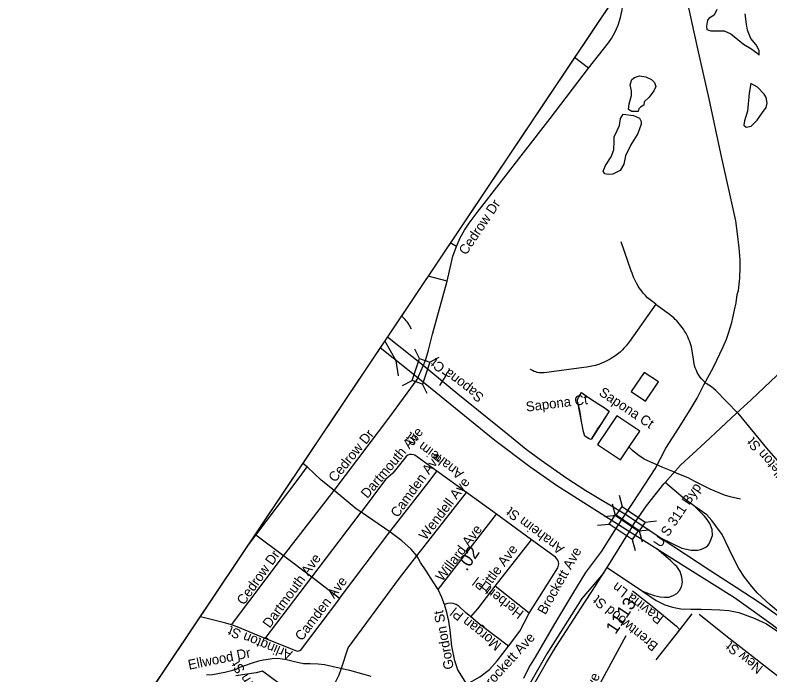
# Model space of a CAD drawing. Extents: x 1715610 to 1720914, y 798298 to 802505.
# Drawn here: x 1715610 to 1715768.9, y 799566.4 to 799705.3 of the extents above; entities that cross this region are included whole.
import ezdxf

# ---------------------------------------------------------------- set-up
doc = ezdxf.new("R2010")
doc.units = 0
doc.layers.add('Default', color=7, linetype='Continuous')
doc.layers.add('Prop DSN Text', color=7, linetype='Continuous')

msp = doc.modelspace()

# ---------------------------------------------------------------- linework, layer by layer
at = {"layer": 'Default'}
for p, q in [((1715825.88, 799842.99), (1715610.03, 799520.5)), ((1715825.88, 799842.99), (1715610.03, 799520.5)), ((1715730.7, 799694.14), (1715727.74, 799696.37)), ((1715695.16, 799633.01), (1715694.16, 799635.02)), ((1715697.32, 799632.28), (1715699.28, 799633.29)), ((1715694.92, 799629.27), (1715695.91, 799631.51)), ((1715700.72, 799629.47), (1715699.9, 799629.99)), ((1715691.58, 799627.37), (1715693.58, 799628.37)), ((1715700.72, 799629.47), (1715699.33, 799627.31)), ((1715696.75, 799625.63), (1715695.75, 799627.64)), ((1715705.01, 799604.81), (1715698.76, 799609.34)), ((1715666.55, 799591.48), (1715677.16, 799605.23)), ((1715694.6, 799591.45), (1715705.01, 799604.81)), ((1715711.32, 799600.23), (1715705.01, 799604.81)), ((1715737.16, 799604.25), (1715737.82, 799601.89)), ((1715735.69, 799602.4), (1715736.36, 799600.05)), ((1715672.49, 799586.97), (1715682.88, 799600.66)), ((1715688.9, 799596.53), (1715682.88, 799600.66)), ((1715699.1, 799584.38), (1715711.32, 799600.23)), ((1715718.75, 799594.88), (1715711.32, 799600.23)), ((1715734.11, 799599.79), (1715736.54, 799600.02)), ((1715732.64, 799597.94), (1715735.08, 799598.17)), ((1715742.62, 799598.6), (1715745.06, 799598.83)), ((1715678.28, 799582.53), (1715688.9, 799596.53)), ((1715741.16, 799596.75), (1715743.59, 799596.98)), ((1715741.37, 799596.77), (1715742.04, 799594.41)), ((1715666.55, 799591.48), (1715660.68, 799595.85)), ((1715711.09, 799585.07), (1715718.75, 799594.88)), ((1715739.91, 799594.92), (1715740.57, 799592.57)), ((1715655.57, 799576.93), (1715666.55, 799591.48)), ((1715672.49, 799586.97), (1715666.55, 799591.48)), ((1715734.62, 799589.05), (1715742.05, 799584.05)), ((1715662.69, 799574.11), (1715672.49, 799586.97)), ((1715678.28, 799582.53), (1715672.49, 799586.97)), ((1715718.2, 799579.41), (1715711.09, 799585.07)), ((1715749.96, 799575.92), (1715752.53, 799579.24)), ((1715649.05, 799578.61), (1715648.94, 799578.63)), ((1715744.98, 799569.62), (1715749.96, 799575.92))]:
    msp.add_line(p, q, dxfattribs=at)
for points in [[(1715730.7, 799694.14), (1715734.91, 799699.49), (1715735.54, 799700.43), (1715736.24, 799701.66), (1715736.94, 799703.2), (1715737.47, 799704.81), (1715737.83, 799706.47), (1715737.98, 799708.09), (1715737.93, 799709.22), (1715737.76, 799710.32), (1715737.57, 799711.06)], [(1715717.08, 799565.74), (1715718.15, 799567.91), (1715719.59, 799570.15), (1715723.6, 799577.2), (1715727.45, 799583.47), (1715730.16, 799587.94), (1715733.51, 799592.45), (1715736.58, 799597.36), (1715738.34, 799600.02), (1715741.46, 799604.77), (1715744.75, 799609.77), (1715747, 799614.15), (1715749.77, 799618.48), (1715752.3, 799622.54), (1715753.57, 799624.68), (1715755.02, 799627.48), (1715757.02, 799631.23), (1715759.08, 799635.51), (1715759.75, 799637.1), (1715760.18, 799638.34), (1715760.91, 799640.63), (1715761.12, 799641.56), (1715761.46, 799643.19), (1715761.8, 799644.74), (1715762.01, 799646.51), (1715762.31, 799647.36), (1715762.54, 799649.97), (1715762.67, 799652.27), (1715762.61, 799653.8), (1715762.46, 799656.35), (1715762.11, 799659.28), (1715761.7, 799662), (1715758.56, 799676.22), (1715756.12, 799687.68), (1715753.74, 799698.23), (1715751.33, 799709.2)], [(1715757.72, 799706.49), (1715757.2, 799705.28), (1715756.13, 799704.65), (1715755.74, 799704.27), (1715755.53, 799703), (1715755.62, 799702.3), (1715756.44, 799702.03), (1715759.25, 799702), (1715760.68, 799701.39), (1715762.15, 799700.2), (1715763.33, 799699.2), (1715764.91, 799698.28), (1715766.15, 799697.38), (1715766.62, 799696.92), (1715766.61, 799697.85), (1715766.02, 799699.1), (1715764.91, 799700.4), (1715764.15, 799702.12), (1715763.94, 799703.39), (1715763.71, 799705.6)], [(1715746.87, 799606.94), (1715750.09, 799610.55), (1715755.24, 799615.32), (1715761.84, 799621.51), (1715764.95, 799624.35), (1715775.71, 799634.47), (1715778.64, 799637.42), (1715780.62, 799639.61), (1715793.86, 799657.02), (1715808.39, 799674), (1715821.8, 799689.38), (1715825.57, 799693.86), (1715826.9, 799695.32), (1715830.61, 799699.38), (1715831.51, 799700.23)], [(1715702.94, 799656.59), (1715703.74, 799658.43), (1715704.63, 799660.04), (1715705.61, 799661.5), (1715707.28, 799663.78), (1715722.64, 799683.54), (1715730.7, 799694.14)], [(1715741.2, 799685.01), (1715739.83, 799685.06), (1715739.13, 799685.44), (1715739.26, 799686.66), (1715739.8, 799688.39), (1715739.76, 799689.37), (1715739.51, 799690.67), (1715739.87, 799691.74), (1715740.41, 799692.16), (1715741.43, 799692.52), (1715742.78, 799692.31), (1715743.98, 799691.77), (1715744.58, 799691.11), (1715744.9, 799690.28), (1715744.46, 799689.36), (1715743.47, 799688.02), (1715742.41, 799687.08), (1715742.34, 799686.34), (1715741.64, 799685.94), (1715741.3, 799685.56), (1715741.2, 799685.01)], [(1715767.72, 799688.66), (1715766.29, 799690.14), (1715764.9, 799690.92), (1715764.56, 799688.87), (1715764.16, 799685.1), (1715763.55, 799683.09), (1715763.43, 799682.14), (1715763.9, 799681.75), (1715764.92, 799681.95), (1715766.21, 799683.22), (1715767.34, 799684.81), (1715768.14, 799685.89), (1715768.31, 799686.8), (1715768.13, 799687.95), (1715767.72, 799688.66)], [(1715738.03, 799684.44), (1715740.21, 799684.19), (1715741.48, 799683.61), (1715741.82, 799682.95), (1715741.83, 799682.33), (1715741.07, 799680.4), (1715739.66, 799678.04), (1715738.51, 799675.67), (1715738.13, 799673.93), (1715737.4, 799672.59), (1715735.84, 799671.81), (1715734.85, 799671.77), (1715734.15, 799671.89), (1715733.77, 799672.49), (1715734.32, 799673.69), (1715735.52, 799675.5), (1715736.07, 799676.96), (1715736.13, 799678.75), (1715736.15, 799679.69), (1715736.78, 799681.01), (1715737.24, 799682.09), (1715737.42, 799683.54), (1715738.03, 799684.44)], [(1715700.95, 799649.3), (1715702.19, 799654.57), (1715702.94, 799656.59)], [(1715702.94, 799656.59), (1715701.63, 799657.35)], [(1715744.86, 799644.46), (1715744.51, 799644.73), (1715743.67, 799645.35), (1715743.16, 799645.81), (1715742.69, 799646.3), (1715742.22, 799646.81), (1715741.94, 799647.17), (1715741.67, 799647.54), (1715741.4, 799647.91), (1715741.15, 799648.29), (1715740.81, 799648.89), (1715740.6, 799649.3), (1715740.4, 799649.7), (1715740.21, 799650.12), (1715740.04, 799650.55), (1715739.88, 799650.99), (1715739.72, 799651.52), (1715737.56, 799657.61)], [(1715700.95, 799649.3), (1715696.95, 799650.36)], [(1715695.91, 799631.51), (1715696.38, 799632.58), (1715697.05, 799634.78), (1715697.9, 799638.16), (1715700.95, 799649.3)], [(1715744.86, 799644.46), (1715739.32, 799636.6), (1715739.06, 799636.24), (1715738.63, 799635.7), (1715738.17, 799635.19), (1715737.84, 799634.87), (1715737.35, 799634.39), (1715736.82, 799633.95), (1715736.28, 799633.54), (1715735.9, 799633.28), (1715735.31, 799632.92), (1715734.72, 799632.59), (1715734.31, 799632.38), (1715733.9, 799632.2), (1715733.48, 799632.02), (1715733.05, 799631.86), (1715732.63, 799631.7), (1715732.18, 799631.58), (1715731.74, 799631.47), (1715731.07, 799631.32), (1715730.4, 799631.21), (1715729.7, 799631.14), (1715721.37, 799630.01), (1715721, 799629.99), (1715720.64, 799629.99), (1715720.29, 799630.03), (1715719.94, 799630.09), (1715719.6, 799630.19), (1715719.27, 799630.32), (1715718.94, 799630.48), (1715718.64, 799630.67), (1715718.63, 799630.68), (1715718.62, 799630.69), (1715718.6, 799630.7), (1715718.6, 799630.7), (1715718.59, 799630.71), (1715718.57, 799630.72), (1715718.56, 799630.72), (1715718.55, 799630.73), (1715718.54, 799630.74), (1715718.53, 799630.75), (1715718.52, 799630.75), (1715718.51, 799630.76), (1715718.51, 799630.77), (1715718.49, 799630.78), (1715718.48, 799630.78)], [(1715762.15, 799621.53), (1715757.53, 799626.26), (1715757.08, 799626.67), (1715756.61, 799627.06), (1715756.07, 799627.44), (1715755.5, 799627.79), (1715755.3, 799627.94), (1715755.05, 799628.19), (1715754.78, 799628.45), (1715754.52, 799628.73), (1715754.22, 799629.13), (1715753.94, 799629.53), (1715753.62, 799630.07), (1715753.42, 799630.51), (1715753.2, 799631.09), (1715753.05, 799631.57), (1715752.97, 799631.94), (1715752.88, 799632.42), (1715752.84, 799632.92), (1715752.37, 799635.48), (1715752.31, 799635.7), (1715752.11, 799636.35), (1715751.94, 799636.78), (1715751.77, 799637.19), (1715751.59, 799637.6), (1715751.39, 799638.01), (1715751.17, 799638.4), (1715750.94, 799638.8), (1715750.7, 799639.17), (1715750.45, 799639.55), (1715750.18, 799639.91), (1715749.9, 799640.26), (1715749.61, 799640.61), (1715749.3, 799640.94), (1715748.99, 799641.27), (1715748.66, 799641.57), (1715748.15, 799642.02), (1715747.79, 799642.3), (1715745.2, 799644.22), (1715744.86, 799644.46)], [(1715693.43, 799639.2), (1715693.03, 799639.99), (1715692.75, 799640.47), (1715692.57, 799640.73), (1715692.37, 799640.98), (1715692.16, 799641.22), (1715691.95, 799641.45), (1715691.69, 799641.69), (1715691.42, 799641.91), (1715691.34, 799641.98)], [(1715688.42, 799637.62), (1715695.89, 799631.6), (1715703.19, 799625.59), (1715713.76, 799617.08), (1715717.61, 799613.92), (1715720.77, 799611.62), (1715726.13, 799607.84), (1715730.13, 799605.26), (1715738.69, 799600.09), (1715740.69, 799598.75)], [(1715690.74, 799629.38), (1715690.26, 799632.55), (1715687.86, 799636.78)], [(1715686.88, 799635.31), (1715692.66, 799630.72), (1715697.43, 799626.88), (1715711, 799615.85), (1715718.34, 799610.29), (1715724, 799606.35), (1715726.84, 799604.55), (1715737.04, 799598.1), (1715739.32, 799596.6)], [(1715739.69, 799626.06), (1715742.73, 799624.04), (1715745.44, 799628.09), (1715742.4, 799630.11), (1715739.69, 799626.06)], [(1715739.69, 799626.06), (1715742.73, 799624.04), (1715745.44, 799628.09), (1715742.4, 799630.11), (1715739.69, 799626.06)], [(1715677.16, 799605.23), (1715688.87, 799620.76), (1715694.63, 799628.63), (1715694.92, 799629.27)], [(1715729.21, 799625.84), (1715730.74, 799624.85), (1715731.89, 799624.06), (1715732.92, 799623.41), (1715734, 799622.68), (1715734.66, 799622.17), (1715735.08, 799621.94), (1715734.38, 799620.84), (1715733.33, 799619.23), (1715732.62, 799618.19), (1715731.85, 799616.98), (1715731.52, 799616.42), (1715731.26, 799615.96), (1715730.85, 799616.14), (1715730.32, 799616.44), (1715729.93, 799616.71), (1715729.67, 799617.57), (1715729.39, 799619.08), (1715729.18, 799620.17), (1715729.04, 799621.27), (1715728.89, 799622.06), (1715728.6, 799623.26), (1715728.47, 799623.77), (1715728.43, 799624.01), (1715728.37, 799624.31), (1715728.62, 799624.83), (1715729, 799625.46), (1715729.21, 799625.84)], [(1715729.21, 799625.84), (1715730.74, 799624.85), (1715732.92, 799623.41), (1715734, 799622.68), (1715735.08, 799621.94), (1715734.38, 799620.84), (1715731.26, 799615.96), (1715730.85, 799616.14), (1715730.32, 799616.44), (1715729.93, 799616.71), (1715729.67, 799617.57), (1715728.47, 799623.77), (1715728.43, 799624.01), (1715728.37, 799624.31), (1715728.62, 799624.83), (1715729.21, 799625.84)], [(1715739.26, 799614.4), (1715741.5, 799617.76), (1715736.67, 799620.96), (1715732.58, 799614.9), (1715737.45, 799611.68), (1715739.26, 799614.4)], [(1715739.26, 799614.4), (1715741.5, 799617.76), (1715736.67, 799620.96), (1715732.58, 799614.9), (1715737.45, 799611.68), (1715739.26, 799614.4)], [(1715762.15, 799621.53), (1715768.19, 799614.13), (1715776.45, 799604.68), (1715777.97, 799603.67), (1715779.93, 799602.56), (1715783.25, 799601.37), (1715784.62, 799600.71), (1715787.64, 799598.32)], [(1715762.7, 799603.44), (1715760.52, 799603.88), (1715759.32, 799604.27), (1715756.29, 799605.55), (1715754.95, 799606.21), (1715753.09, 799607.11), (1715751.66, 799607.87), (1715749.38, 799608.85), (1715748.46, 799609.21), (1715746.39, 799610.11), (1715742.4, 799611.83), (1715741.07, 799612.74), (1715739.99, 799613.63), (1715739.34, 799614.29), (1715739.26, 799614.4)], [(1715698.76, 799609.34), (1715694.17, 799612.65), (1715693.87, 799612.78), (1715693.43, 799612.83), (1715693.05, 799612.79), (1715692.69, 799612.66), (1715692.33, 799612.41), (1715689.54, 799608.9), (1715688, 799607.53), (1715682.88, 799600.66)], [(1715671.51, 799610.22), (1715670.56, 799610.94)], [(1715660.68, 799595.85), (1715669.81, 799607.87), (1715671.51, 799610.22)], [(1715677.16, 799605.23), (1715674.46, 799607.44), (1715671.51, 799610.22)], [(1715688.9, 799596.53), (1715697.21, 799607.16), (1715698.76, 799609.34)], [(1715740.69, 799598.75), (1715742.94, 799602.01), (1715746.58, 799606.62), (1715746.87, 799606.94)], [(1715753.08, 799601.84), (1715750.66, 799603.72), (1715746.87, 799606.94)], [(1715682.88, 799600.66), (1715681.8, 799601.4), (1715677.16, 799605.23)], [(1715746.03, 799595.18), (1715750.37, 799593.13), (1715752.35, 799592.68), (1715753.75, 799592.65), (1715754.32, 799592.79), (1715754.84, 799593.02), (1715755.39, 799593.33), (1715755.8, 799593.65), (1715756.08, 799594.04), (1715756.48, 799594.82), (1715756.82, 799595.76), (1715756.74, 799597.01), (1715756.23, 799598.26), (1715755.67, 799599.16), (1715755.12, 799599.86), (1715753.08, 799601.84)], [(1715776.16, 799574.89), (1715771.29, 799579.22), (1715768.96, 799581.16), (1715766.28, 799583.63), (1715765.11, 799585), (1715763.55, 799587.01), (1715762.39, 799588.8), (1715761.07, 799591.24), (1715758.82, 799595.97), (1715757.47, 799597.85), (1715756.64, 799598.93), (1715755.59, 799600.13), (1715753.08, 799601.84)], [(1715739.32, 799596.6), (1715740.36, 799598.29), (1715740.69, 799598.75)], [(1715740.69, 799598.75), (1715746.03, 799595.18)], [(1715694.6, 799591.45), (1715693.39, 799592.92), (1715691.45, 799594.63), (1715688.9, 799596.53)], [(1715734.62, 799589.05), (1715739.32, 799596.6)], [(1715739.32, 799596.6), (1715744.62, 799593.28), (1715745.02, 799593.02)], [(1715658.73, 799593.25), (1715660.68, 799595.85)], [(1715718.2, 799579.41), (1715724.27, 799588.93), (1715724.48, 799589.81), (1715724.37, 799590.25), (1715724.29, 799590.58), (1715723.8, 799591.22), (1715718.75, 799594.88)], [(1715746.03, 799595.18), (1715756.44, 799588.31), (1715761.78, 799584.91), (1715767.03, 799581.47), (1715776.16, 799574.89)], [(1715742.05, 799584.05), (1715743.36, 799583.54), (1715744.54, 799583.15), (1715745.78, 799582.86), (1715746.69, 799582.76), (1715747.63, 799582.81), (1715748.55, 799583.1), (1715749.3, 799583.53), (1715749.84, 799584.18), (1715750.27, 799584.98), (1715750.47, 799585.93), (1715750.39, 799586.99), (1715750.01, 799588.15), (1715749.34, 799589.23), (1715748.96, 799589.53), (1715748.08, 799590.41), (1715745.02, 799593.02)], [(1715745.02, 799593.02), (1715750.91, 799589.33), (1715761.44, 799582.68), (1715764.86, 799580.27), (1715769.37, 799576.99), (1715774.41, 799573.05)], [(1715675.99, 799562.27), (1715677.14, 799564.16), (1715678.24, 799566.46), (1715678.75, 799567.81), (1715680.1, 799572.11), (1715690.96, 799586.76), (1715694.6, 799591.45)], [(1715699.1, 799584.38), (1715697.87, 799586.22), (1715696.55, 799588.35), (1715695.39, 799590.09), (1715694.6, 799591.45)], [(1715733.84, 799587.8), (1715734.62, 799589.05)], [(1715733.84, 799587.8), (1715729.32, 799582.48), (1715721.94, 799570.86), (1715717.48, 799562.96), (1715715.52, 799559.19), (1715714.52, 799556.87), (1715713.46, 799552.5), (1715713.22, 799550.57), (1715713.19, 799548.01), (1715714.27, 799537.69), (1715715.14, 799530.33), (1715715.35, 799527.47), (1715715.67, 799525.51), (1715715.93, 799521.37), (1715715.92, 799518.22), (1715715.57, 799515.43), (1715714.81, 799512.55), (1715713.86, 799509.92), (1715711.38, 799504.12), (1715707.11, 799495.36)], [(1715707.79, 799494.65), (1715712.08, 799503.42), (1715714.29, 799508.12), (1715714.94, 799509.43), (1715715.94, 799512.15), (1715716.75, 799515.1), (1715716.87, 799516.33), (1715716.97, 799520.41), (1715716.62, 799524.27), (1715716.37, 799527.29), (1715715.69, 799533.91), (1715714.76, 799541.07), (1715714.06, 799547.26), (1715713.99, 799549.57), (1715714.18, 799551.78), (1715714.68, 799554.51), (1715715.42, 799556.88), (1715716.77, 799559.87), (1715717.47, 799561.27), (1715721.86, 799569.03), (1715723.8, 799572.16), (1715729.96, 799581.74), (1715731.53, 799584.15), (1715733.84, 799587.8)], [(1715705.93, 799578.66), (1715707.4, 799580.35), (1715711.09, 799585.07)], [(1715700.38, 799581.24), (1715699.84, 799582.72), (1715699.1, 799584.38)], [(1715740.01, 799584.12), (1715740.52, 799583.69), (1715744.1, 799580.87), (1715749.23, 799576.68), (1715749.96, 799575.92)], [(1715742.05, 799584.05), (1715744.98, 799582.09), (1715746.76, 799581.19), (1715748.43, 799580.68), (1715750.13, 799580.35), (1715752.25, 799580.25), (1715754.46, 799580.23), (1715756.58, 799580.17), (1715758.34, 799580.13), (1715760.28, 799579.96), (1715762.34, 799579.56), (1715765.58, 799578.36), (1715767.26, 799577.62), (1715768.18, 799577.13), (1715769.75, 799576.13), (1715774.41, 799573.05)], [(1715678.28, 799582.53), (1715670.03, 799571.57), (1715669.87, 799571.51), (1715669.46, 799571.35), (1715662.69, 799574.11)], [(1715705.93, 799578.66), (1715704.83, 799579.57), (1715703.48, 799580.82), (1715702.83, 799581.24), (1715702.25, 799581.43), (1715701.64, 799581.51), (1715701.03, 799581.45), (1715700.38, 799581.24)], [(1715705.11, 799564.49), (1715703.24, 799567.47), (1715702.58, 799569.36), (1715701.97, 799572.43), (1715701.61, 799575.85), (1715701.31, 799577.72), (1715700.88, 799579.57), (1715700.38, 799581.24)], [(1715649.05, 799578.61), (1715649.26, 799579.11)], [(1715713.85, 799572.49), (1715716.24, 799575.63), (1715718.2, 799579.41)], [(1715754.02, 799579.23), (1715760.28, 799574.22), (1715772.58, 799564.61), (1715778.97, 799560.32)], [(1715655.57, 799576.93), (1715654.37, 799577.34), (1715649.05, 799578.61)], [(1715713.85, 799572.49), (1715707.87, 799577.03), (1715705.93, 799578.66)], [(1715662.69, 799574.11), (1715656.74, 799576.54), (1715655.57, 799576.93)], [(1715722.62, 799541.75), (1715722.63, 799543.89), (1715722.9, 799545.64), (1715723.25, 799546.84), (1715723.63, 799547.61), (1715724.15, 799548.39), (1715727.38, 799552.24), (1715728.33, 799553.7), (1715729.47, 799556.13), (1715730.8, 799559.67), (1715731.85, 799562.13), (1715738.61, 799574.72)], [(1715705.11, 799564.49), (1715707.86, 799566.04), (1715709.89, 799567.57), (1715711.49, 799569.38), (1715713.85, 799572.49)], [(1715650.3, 799566.4), (1715651.59, 799566.52), (1715654.16, 799566.98), (1715655.87, 799567.39), (1715656.57, 799567.65), (1715657.35, 799568.01), (1715658.16, 799568.35), (1715659.99, 799568.95), (1715661.32, 799569.36), (1715662.25, 799569.57), (1715662.86, 799569.68), (1715664.11, 799569.88), (1715665.35, 799569.93), (1715667.16, 799569.64), (1715668.81, 799569.2), (1715670.72, 799568.84), (1715672.17, 799568.8), (1715673.81, 799568.74), (1715675.15, 799568.61), (1715680.42, 799567.38), (1715683.45, 799566.57), (1715684.91, 799566.16)], [(1715671.24, 799558), (1715669.69, 799560.48), (1715668.78, 799561.62), (1715667.79, 799562.71), (1715665.88, 799564.42), (1715662.13, 799567.21), (1715660.8, 799566.85), (1715656.46, 799566.23)]]:
    msp.add_lwpolyline(points, dxfattribs=at)
for points in [[(1715693.58, 799628.37), (1715695.15, 799633.01), (1715697.32, 799632.28), (1715695.75, 799627.64)], [(1715737.82, 799601.89), (1715742.63, 799598.6), (1715741.35, 799596.73), (1715736.54, 799600.02)], [(1715736.36, 799600.05), (1715741.16, 799596.76), (1715739.88, 799594.89), (1715735.08, 799598.17)]]:
    msp.add_lwpolyline(points, close=True, dxfattribs=at)
at = {"layer": 'Prop DSN Text'}
msp.add_lwpolyline([(1715972.32, 799278.02), (1716250.51, 799693.66), (1715888.23, 799936.14), (1715610.03, 799520.5)], close=True, dxfattribs=at)

# ---------------------------------------------------------------- texts
at = {"layer": 'Default'}
for s, height, rotation, p in [('Cedrow Dr', 2.066, 56.2051, (1715704.96, 799654.65)), ('Sapona Ct', 2.066, 142.6258, (1715708.87, 799625.25)), ('Sapona Ct', 2.066, 326.3007, (1715732.75, 799625.43)), ('Sapona Ct', 2.066, 7.0417, (1715717.67, 799621.83)), ('Dartmouth Ave', 2.0663, 49.8283, (1715684.18, 799603.42)), ('Cedrow Dr', 2.066, 50.8512, (1715677.38, 799606.82)), ('Anaheim St', 2.066, 143.0271, (1715704.6, 799609.07)), ('Pendleton St', 2.0663, 131.3961, (1715775.86, 799604.75)), ('Camden Ave', 2.066, 53.9446, (1715690.55, 799599.4)), ('Wendell Ave', 2.0663, 52.8762, (1715696.47, 799594.64)), ('U S 311 Byp', 2.0663, 56.2051, (1715745.94, 799593.08)), ('Anaheim St', 2.066, 143.0271, (1715725.79, 799593.28)), ('Willard Ave', 2.0663, 52.7017, (1715699.98, 799585.94)), ('.02', 2.719, 55.3005, (1715705.07, 799588.11)), ('Little Ave', 2.066, 53.0635, (1715709.09, 799583.8)), ('Brockett Ave', 2.0663, 60.5842, (1715721.64, 799578.94)), ('Cedrow Dr', 2.066, 54.4063, (1715658.18, 799580.97)), ('Dartmouth Ave', 2.0663, 53.749, (1715663.62, 799576.12)), ('Camden Ave', 2.066, 52.7426, (1715670.39, 799573.42)), ('Herbert Pl', 2.066, 142.9868, (1715717.27, 799579.69)), ('Ravina Ln', 2.066, 142.9253, (1715746.65, 799578.55)), ('Brentwood St', 2.0663, 140.7308, (1715745.53, 799572.81)), ('1113', 2.719, 56.2051, (1715736.41, 799574.8)), ('Morgan Pl', 2.066, 141.5656, (1715712.55, 799572.94)), ('Gordon St', 2.066, 100.33, (1715702.39, 799567.75)), ('Arlington St', 2.0663, 157.6641, (1715668.58, 799571.32)), ('Brockett Ave', 2.0663, 47.7257, (1715709.07, 799562.58)), ('New St', 2.066, 141.7034, (1715767.62, 799568.08)), ('Ellwood Dr', 2.066, 11.4259, (1715646.65, 799567.49)), ('Ashburn St', 2.066, 122.0781, (1715664.39, 799558.11)), ('Lamb Ave', 2.066, 66.9807, (1715728.33, 799554.85))]:
    msp.add_text(s, height=height, rotation=rotation, dxfattribs=at).set_placement(p)

doc.saveas('drawing.dxf')
